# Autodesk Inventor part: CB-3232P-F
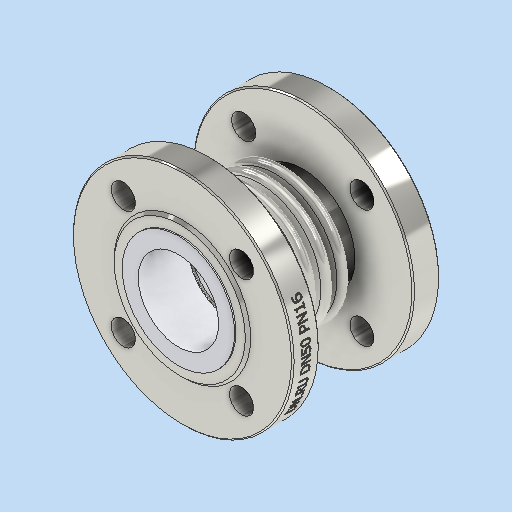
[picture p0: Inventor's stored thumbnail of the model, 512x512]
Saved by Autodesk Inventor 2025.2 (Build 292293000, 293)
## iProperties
Company: DN.RU
Created: 2026-04
Part Number: CB-3232P-F
Material: Типовые
Document SubType Name: Modeling
Designer: DN.RU
Density: 6.53951 g/cm^3
Appearance: По умолчанию
Description: D140-02138
Mass: 5000 g
Surface Area: 2002.76 cm^2
Volume: 822.35 cm^3
Author: DN.RU
Title: Компенсатор сильфонный осевой DN.ru Ду50 Ру16
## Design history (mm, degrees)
sketch "Эскиз1"
  geometry: L1 (0, 0)-(0, -55); L2 (36, -55)-(36, 0); L3 (36, 0)-(0, 0); L4 (36, 0)-(36, -6); L5 (26, -6)-(46, -6); L6 (26, -9.5)-(46, -9.5); L7 (46, -2.5)-(26, -2.5); L8 (46, -7.5)-(26, -7.5); L9 (26, -4.5)-(46, -4.5); L10 (46, -14.5)-(26, -14.5); L11 (26, -16.5)-(46, -16.5); L12 (26, -18)-(46, -18); L13 (26, -21.5)-(46, -21.5); L14 (46, -19.5)-(26, -19.5); L15 (0, -55)-(36, -55); L16 (36, -55)-(30, -55); L17 (30, -55)-(30, -19.5); L18 (36, -16.5)-(34, -16.5); L19 (34, -16.5)-(34, -7.5); L20 (36, -4.5)-(34, -4.5); L21 (34, -4.5)-(34, 0); L22 (0, -55)-(0, -35); L23 (0, -35)-(82.5, -35); L24 (82.5, -35)-(82.5, -55); L25 (82.5, -55)-(0, -55); L26 (36, -35)-(36, -45); L27 (36, -45)-(39, -45); L28 (39, -45)-(39, -35); L29 (39, -35)-(36, -35); A1 r 3.5 centre (26, -6) between (26, -2.5) and (26, -9.5); A2 r 3.5 centre (46, -6) between (46, -9.5) and (46, -2.5); A3 r 1.5 centre (26, -6) between (26, -4.5) and (26, -7.5); A4 r 1.5 centre (46, -6) between (46, -7.5) and (46, -4.5); A5 r 1.5 centre (26, -18) between (26, -16.5) and (26, -19.5); A6 r 3.5 centre (26, -18) between (26, -14.5) and (26, -21.5); A7 r 1.5 centre (46, -18) between (46, -19.5) and (46, -16.5); A8 r 3.5 centre (46, -18) between (46, -21.5) and (46, -14.5); 19 further points
  constraints: 62 end point, 16 point on circle, 14 point on line, 8 centre point, 7 parallel, 4 perpendicular, 4 tangent, 3 midpoint, 2 vertical, 1 horizontal, 25 other
  dimensions: "d0" = 55 distance of L1.start L1.end; "d3" = 6 distance of L2.end L4.end; "d4" = 10 distance of L4.end L5.end; "d5" = 7 diameter of A2; "d6" = 2 distance between parallel lines of L6 L8; "d9" = 12 distance of L4.end point (36, -18); "d18" = 2 distance of L18.start L18.end; "d19" = 2 distance of L20.start L20.end; "d27" = 30 distance between parallel lines of L1 L17; "d28" = 6 distance between parallel lines of L2 L17; "d29" = 20 distance of L1.end L22.end; "d30" = 82.5 distance of L22.end L23.end; "d31" = 10 distance of L26.start L26.end; "d32" = 3 distance of L27.end L26.end
revolve "Вращение1" sketch "Эскиз1" stored, may be unused: angle "d20" = 360 deg
sketch "Эскиз3" dims "d33" = 125
  geometry: L1 (0, 0)-(54.414, 54.414); L2 (0, 0)-(76.954, 0); C1 r 9 at (44.194, 44.194); C2 r 9 at (-44.194, 44.194); C3 r 9 at (-44.194, -44.194); C4 r 9 at (44.194, -44.194); C5 r 30 at (0, 0) reference; C6 r 51 at (0, 0); C7 r 82.5 at (0, 0) reference; 1 further point
  constraints: 5 centre point, 4 end point, 2 coincident, 1 equal length, 1 horizontal, 1 point on line, 12 other
  dimensions: "d34" = 45 deg angle of L2 L1; "d35" = 18 diameter of C1; "d38" = 360 deg dimension on point (0, 0) C1.centre (derived); "d40" = 102 diameter of C6
  node "Эскиз — круговой массив1" dims "d38" = 360 deg (derived)
extrude "Выдавливание1" cut sketch "Эскиз3" stored distance "d41" = 10; taper "d42" = 0 deg
extrude "Выдавливание2" join sketch "Эскиз3" distance "d43" = 2; taper "d44" = 0 deg
chamfer "Фаска2" distance "d45" = 2; stored, may be unused: second distance "d46" = 2, angle "d47" = 45 deg
chamfer "Фаска3" distance "d48" = 1; stored, may be unused: second distance "d49" = 2, angle "d50" = 45 deg
mirror "Зеркальное отражение2"
fillet "Сопряжение2" dims "d51" = 1
node "РабПлоскость2"
sketch "Эскиз4"
  geometry: L1 (-44.383, 3.589)-(46.395, 3.589); L2 (46.395, 3.589)-(46.395, 0.413); L3 (46.395, 0.413)-(-44.383, 0.413); L4 (-44.383, 0.413)-(-44.383, 3.589); 1 further point
  constraints: 2 other
feature "Рельеф2" sketch "Эскиз4" dims "d3" = 6, "d52" = 0.1, "d53" = 0
sketch "Эскиз5"
  geometry: C1 r 30 at (0, 0) reference; C2 r 42 at (0, 0); 1 further point
  constraints: 1 centre point
  dimensions: "d54" = 12 radial gap between concentric circles of C1 C2
extrude "Выдавливание3" join sketch "Эскиз5" distance "d55" = 1; taper "d56" = 0 deg
mirror "Зеркальное отражение3"
node "Твердое тело1"
node "Эскиз — прямоугольный массив1" dims "d9" = 12, "d12" = 10
